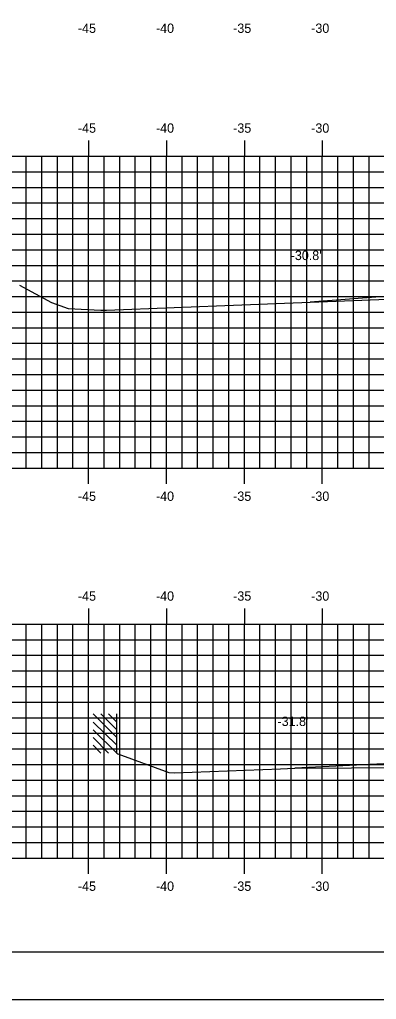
# Model space of a CAD drawing. Extents: x 1048345 to 1048515, y 781148 to 781258.
# Drawn here: x 1048378.4 to 1048401.3, y 781148.2 to 781211 of the extents above; entities that cross this region are included whole.
import ezdxf

# ---------------------------------------------------------------- set-up
doc = ezdxf.new("R2010")
doc.units = 0
for name, color, linetype in [('ANNOTATION', 7, 'Continuous'), ('BORDER', 7, 'Continuous'), ('D_Roadway_Pavement', 7, 'Continuous'), ('D_Roadway_SubGrade', 7, 'Continuous'), ('H_V ANNOTATION', 7, 'Continuous'), ('MAJOR', 7, 'Continuous'), ('MINOR', 7, 'Continuous'), ('PLOT BOUNDARY', 7, 'Continuous'), ('S_Buildings', 7, 'Continuous'), ('S_Roadway_Centerline', 7, 'Continuous')]:
    doc.layers.add(name, color=color, linetype=linetype)

msp = doc.modelspace()

# ---------------------------------------------------------------- linework, layer by layer
msp.add_lwpolyline([(1048396.895, 781163.024), (1048396.94, 781163.031)])
at = {"layer": 'BORDER'}
msp.add_lwpolyline([(1048352.833, 781151.252), (1048512.833, 781151.252), (1048512.833, 781256.252), (1048352.833, 781256.252)], close=True, dxfattribs=at)
at = {"layer": 'D_Roadway_Pavement'}
msp.add_line((1048401.78, 781163.286), (1048396.063, 781163.02), dxfattribs=at)
at = {"layer": 'D_Roadway_SubGrade'}
msp.add_line((1048401.824, 781193.246), (1048397.06, 781192.89), dxfattribs=at)
at = {"layer": 'MAJOR'}
for p, q in [((1048382.832, 781203.254), (1048382.832, 781202.252)), ((1048387.832, 781203.254), (1048387.832, 781202.252)), ((1048392.832, 781203.254), (1048392.832, 781202.252)), ((1048397.832, 781203.254), (1048397.832, 781202.252)), ((1048357.832, 781202.252), (1048497.832, 781202.252)), ((1048357.832, 781202.252), (1048497.832, 781202.252)), ((1048357.832, 781202.252), (1048497.832, 781202.252)), ((1048382.832, 781182.252), (1048382.832, 781202.252)), ((1048382.832, 781182.252), (1048382.832, 781202.252)), ((1048387.832, 781182.252), (1048387.832, 781202.252)), ((1048387.832, 781182.252), (1048387.832, 781202.252)), ((1048392.832, 781182.252), (1048392.832, 781202.252)), ((1048392.832, 781182.252), (1048392.832, 781202.252)), ((1048397.832, 781182.252), (1048397.832, 781202.252)), ((1048397.832, 781182.252), (1048397.832, 781202.252)), ((1048357.832, 781197.252), (1048497.832, 781197.252)), ((1048357.832, 781197.252), (1048497.832, 781197.252)), ((1048357.832, 781192.252), (1048497.832, 781192.252)), ((1048357.832, 781192.252), (1048497.832, 781192.252)), ((1048357.832, 781187.252), (1048497.832, 781187.252)), ((1048357.832, 781187.252), (1048497.832, 781187.252)), ((1048357.832, 781182.252), (1048497.832, 781182.252)), ((1048357.832, 781182.252), (1048497.832, 781182.252)), ((1048357.832, 781182.252), (1048497.832, 781182.252)), ((1048382.832, 781181.25), (1048382.832, 781182.252)), ((1048387.832, 781181.25), (1048387.832, 781182.252)), ((1048392.832, 781181.25), (1048392.832, 781182.252)), ((1048397.832, 781181.25), (1048397.832, 781182.252)), ((1048382.832, 781173.254), (1048382.832, 781172.252)), ((1048387.832, 781173.254), (1048387.832, 781172.252)), ((1048392.832, 781173.254), (1048392.832, 781172.252)), ((1048397.832, 781173.254), (1048397.832, 781172.252)), ((1048357.832, 781172.252), (1048497.832, 781172.252)), ((1048357.832, 781172.252), (1048497.832, 781172.252)), ((1048382.832, 781157.252), (1048382.832, 781172.252)), ((1048387.832, 781157.252), (1048387.832, 781172.252)), ((1048392.832, 781157.252), (1048392.832, 781172.252)), ((1048397.832, 781157.252), (1048397.832, 781172.252)), ((1048357.832, 781167.252), (1048497.832, 781167.252)), ((1048357.832, 781162.252), (1048497.832, 781162.252)), ((1048357.832, 781157.252), (1048497.832, 781157.252)), ((1048357.832, 781157.252), (1048497.832, 781157.252)), ((1048382.832, 781156.25), (1048382.832, 781157.252)), ((1048387.832, 781156.25), (1048387.832, 781157.252)), ((1048392.832, 781156.25), (1048392.832, 781157.252)), ((1048397.832, 781156.25), (1048397.832, 781157.252))]:
    msp.add_line(p, q, dxfattribs=at)
at = {"layer": 'MINOR'}
for p, q in [((1048378.832, 781182.252), (1048378.832, 781202.252)), ((1048378.832, 781182.252), (1048378.832, 781202.252)), ((1048379.832, 781182.252), (1048379.832, 781202.252)), ((1048379.832, 781182.252), (1048379.832, 781202.252)), ((1048380.832, 781182.252), (1048380.832, 781202.252)), ((1048380.832, 781182.252), (1048380.832, 781202.252)), ((1048381.832, 781182.252), (1048381.832, 781202.252)), ((1048381.832, 781182.252), (1048381.832, 781202.252)), ((1048383.832, 781182.252), (1048383.832, 781202.252)), ((1048383.832, 781182.252), (1048383.832, 781202.252)), ((1048384.832, 781182.252), (1048384.832, 781202.252)), ((1048384.832, 781182.252), (1048384.832, 781202.252)), ((1048385.832, 781182.252), (1048385.832, 781202.252)), ((1048385.832, 781182.252), (1048385.832, 781202.252)), ((1048386.832, 781182.252), (1048386.832, 781202.252)), ((1048386.832, 781182.252), (1048386.832, 781202.252)), ((1048388.832, 781182.252), (1048388.832, 781202.252)), ((1048388.832, 781182.252), (1048388.832, 781202.252)), ((1048389.832, 781182.252), (1048389.832, 781202.252)), ((1048389.832, 781182.252), (1048389.832, 781202.252)), ((1048390.832, 781182.252), (1048390.832, 781202.252)), ((1048390.832, 781182.252), (1048390.832, 781202.252)), ((1048391.832, 781182.252), (1048391.832, 781202.252)), ((1048391.832, 781182.252), (1048391.832, 781202.252)), ((1048393.832, 781182.252), (1048393.832, 781202.252)), ((1048393.832, 781182.252), (1048393.832, 781202.252)), ((1048394.832, 781182.252), (1048394.832, 781202.252)), ((1048394.832, 781182.252), (1048394.832, 781202.252)), ((1048395.832, 781182.252), (1048395.832, 781202.252)), ((1048395.832, 781182.252), (1048395.832, 781202.252)), ((1048396.832, 781182.252), (1048396.832, 781202.252)), ((1048396.832, 781182.252), (1048396.832, 781202.252)), ((1048398.832, 781182.252), (1048398.832, 781202.252)), ((1048398.832, 781182.252), (1048398.832, 781202.252)), ((1048399.832, 781182.252), (1048399.832, 781202.252)), ((1048399.832, 781182.252), (1048399.832, 781202.252)), ((1048400.832, 781182.252), (1048400.832, 781202.252)), ((1048400.832, 781182.252), (1048400.832, 781202.252)), ((1048357.832, 781201.252), (1048497.832, 781201.252)), ((1048357.832, 781201.252), (1048497.832, 781201.252)), ((1048357.832, 781200.252), (1048497.832, 781200.252)), ((1048357.832, 781200.252), (1048497.832, 781200.252)), ((1048357.832, 781199.252), (1048497.832, 781199.252)), ((1048357.832, 781199.252), (1048497.832, 781199.252)), ((1048357.832, 781198.252), (1048497.832, 781198.252)), ((1048357.832, 781198.252), (1048497.832, 781198.252)), ((1048357.832, 781196.252), (1048497.832, 781196.252)), ((1048357.832, 781196.252), (1048497.832, 781196.252)), ((1048357.832, 781195.252), (1048497.832, 781195.252)), ((1048357.832, 781195.252), (1048497.832, 781195.252)), ((1048357.832, 781194.252), (1048497.832, 781194.252)), ((1048357.832, 781194.252), (1048497.832, 781194.252)), ((1048357.832, 781193.252), (1048497.832, 781193.252)), ((1048357.832, 781193.252), (1048497.832, 781193.252)), ((1048357.832, 781191.252), (1048497.832, 781191.252)), ((1048357.832, 781191.252), (1048497.832, 781191.252)), ((1048357.832, 781190.252), (1048497.832, 781190.252)), ((1048357.832, 781190.252), (1048497.832, 781190.252)), ((1048357.832, 781189.252), (1048497.832, 781189.252)), ((1048357.832, 781189.252), (1048497.832, 781189.252)), ((1048357.832, 781188.252), (1048497.832, 781188.252)), ((1048357.832, 781188.252), (1048497.832, 781188.252)), ((1048357.832, 781186.252), (1048497.832, 781186.252)), ((1048357.832, 781186.252), (1048497.832, 781186.252)), ((1048357.832, 781185.252), (1048497.832, 781185.252)), ((1048357.832, 781185.252), (1048497.832, 781185.252)), ((1048357.832, 781184.252), (1048497.832, 781184.252)), ((1048357.832, 781184.252), (1048497.832, 781184.252)), ((1048357.832, 781183.252), (1048497.832, 781183.252)), ((1048357.832, 781183.252), (1048497.832, 781183.252)), ((1048378.832, 781157.252), (1048378.832, 781172.252)), ((1048379.832, 781157.252), (1048379.832, 781172.252)), ((1048380.832, 781157.252), (1048380.832, 781172.252)), ((1048381.832, 781157.252), (1048381.832, 781172.252)), ((1048383.832, 781157.252), (1048383.832, 781172.252)), ((1048384.832, 781157.252), (1048384.832, 781172.252)), ((1048385.832, 781157.252), (1048385.832, 781172.252)), ((1048386.832, 781157.252), (1048386.832, 781172.252)), ((1048388.832, 781157.252), (1048388.832, 781172.252)), ((1048389.832, 781157.252), (1048389.832, 781172.252)), ((1048390.832, 781157.252), (1048390.832, 781172.252)), ((1048391.832, 781157.252), (1048391.832, 781172.252)), ((1048393.832, 781157.252), (1048393.832, 781172.252)), ((1048394.832, 781157.252), (1048394.832, 781172.252)), ((1048395.832, 781157.252), (1048395.832, 781172.252)), ((1048396.832, 781157.252), (1048396.832, 781172.252)), ((1048398.832, 781157.252), (1048398.832, 781172.252)), ((1048399.832, 781157.252), (1048399.832, 781172.252)), ((1048400.832, 781157.252), (1048400.832, 781172.252)), ((1048357.832, 781171.252), (1048497.832, 781171.252)), ((1048357.832, 781170.252), (1048497.832, 781170.252)), ((1048357.832, 781169.252), (1048497.832, 781169.252)), ((1048357.832, 781168.252), (1048497.832, 781168.252)), ((1048357.832, 781166.252), (1048497.832, 781166.252)), ((1048357.832, 781165.252), (1048497.832, 781165.252)), ((1048357.832, 781164.252), (1048497.832, 781164.252)), ((1048357.832, 781163.252), (1048497.832, 781163.252)), ((1048357.832, 781161.252), (1048497.832, 781161.252)), ((1048357.832, 781160.252), (1048497.832, 781160.252)), ((1048357.832, 781159.252), (1048497.832, 781159.252)), ((1048357.832, 781158.252), (1048497.832, 781158.252))]:
    msp.add_line(p, q, dxfattribs=at)
at = {"layer": 'PLOT BOUNDARY'}
msp.add_lwpolyline([(1048344.739, 781148.193), (1048514.739, 781148.193), (1048514.739, 781258.193), (1048344.739, 781258.193)], close=True, dxfattribs=at)
at = {"layer": 'S_Buildings'}
for p, q in [((1048384.638, 781164.988), (1048383.129, 781166.497)), ((1048384.638, 781164.496), (1048383.129, 781165.972)), ((1048384.638, 781165.48), (1048383.621, 781166.497)), ((1048384.638, 781165.972), (1048384.113, 781166.497)), ((1048384.638, 781163.971), (1048384.638, 781166.497)), ((1048384.638, 781163.971), (1048383.129, 781165.48)), ((1048384.113, 781163.971), (1048383.129, 781164.988)), ((1048383.621, 781163.971), (1048383.129, 781164.496))]:
    msp.add_line(p, q, dxfattribs=at)
at = {"layer": 'S_Roadway_Centerline'}
for points in [[(1048378.404, 781193.971), (1048380.444, 781192.878), (1048381.518, 781192.487), (1048383.629, 781192.368), (1048383.98, 781192.382), (1048392.669, 781192.719), (1048401.451, 781193.061), (1048401.471, 781193.059), (1048406.922, 781193.087), (1048409.89, 781193.252), (1048415.467, 781193.603), (1048421.353, 781193.835), (1048427.506, 781194.095), (1048431.344, 781194.1), (1048434.132, 781194.08), (1048434.162, 781194.088), (1048439.882, 781194.008), (1048443.963, 781193.943), (1048453.31, 781193.879), (1048463.018, 781193.897), (1048464.051, 781193.889), (1048465.593, 781193.896), (1048488.39, 781193.918), (1048497.832, 781193.927)], [(1048384.638, 781163.971), (1048384.708, 781163.934), (1048387.982, 781162.741), (1048388.35, 781162.72), (1048395.158, 781162.984), (1048395.608, 781163.002), (1048396.063, 781163.02), (1048396.064, 781163.02), (1048406.97, 781163.076), (1048412.908, 781163.406), (1048415.553, 781163.573), (1048427.238, 781164.033), (1048427.497, 781164.041), (1048427.683, 781164.038), (1048439.979, 781163.865), (1048448.984, 781163.722)]]:
    msp.add_lwpolyline(points, dxfattribs=at)

# ---------------------------------------------------------------- texts
at = {"layer": 'ANNOTATION'}
msp.add_text("-30.8'", height=0.6, dxfattribs=at).set_placement((1048395.805, 781195.59))
msp.add_text("-31.8'", height=0.6, rotation=360, dxfattribs=at).set_placement((1048394.958, 781165.72))
at = {"layer": 'H_V ANNOTATION'}
for s, p in [('-45', (1048382.15, 781210.152)), ('-40', (1048387.158, 781210.152)), ('-35', (1048392.113, 781210.152)), ('-30', (1048397.121, 781210.152)), ('-45', (1048382.15, 781203.752)), ('-40', (1048387.158, 781203.752)), ('-35', (1048392.113, 781203.752)), ('-30', (1048397.121, 781203.752)), ('-45', (1048382.15, 781180.152)), ('-40', (1048387.158, 781180.152)), ('-35', (1048392.113, 781180.152)), ('-30', (1048397.121, 781180.152)), ('-45', (1048382.15, 781173.752)), ('-40', (1048387.158, 781173.752)), ('-35', (1048392.113, 781173.752)), ('-30', (1048397.121, 781173.752)), ('-45', (1048382.15, 781155.152)), ('-40', (1048387.158, 781155.152)), ('-35', (1048392.113, 781155.152)), ('-30', (1048397.121, 781155.152))]:
    msp.add_text(s, height=0.6, dxfattribs=at).set_placement(p)

doc.saveas('drawing.dxf')
